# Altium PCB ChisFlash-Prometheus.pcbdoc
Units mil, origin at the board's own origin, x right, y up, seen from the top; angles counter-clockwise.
Board outline 4825.59 x 2046 mil, 2 copper layers (Top Layer, Bottom Layer); 14 components, 55 nets, 238 pads, 204 vias.
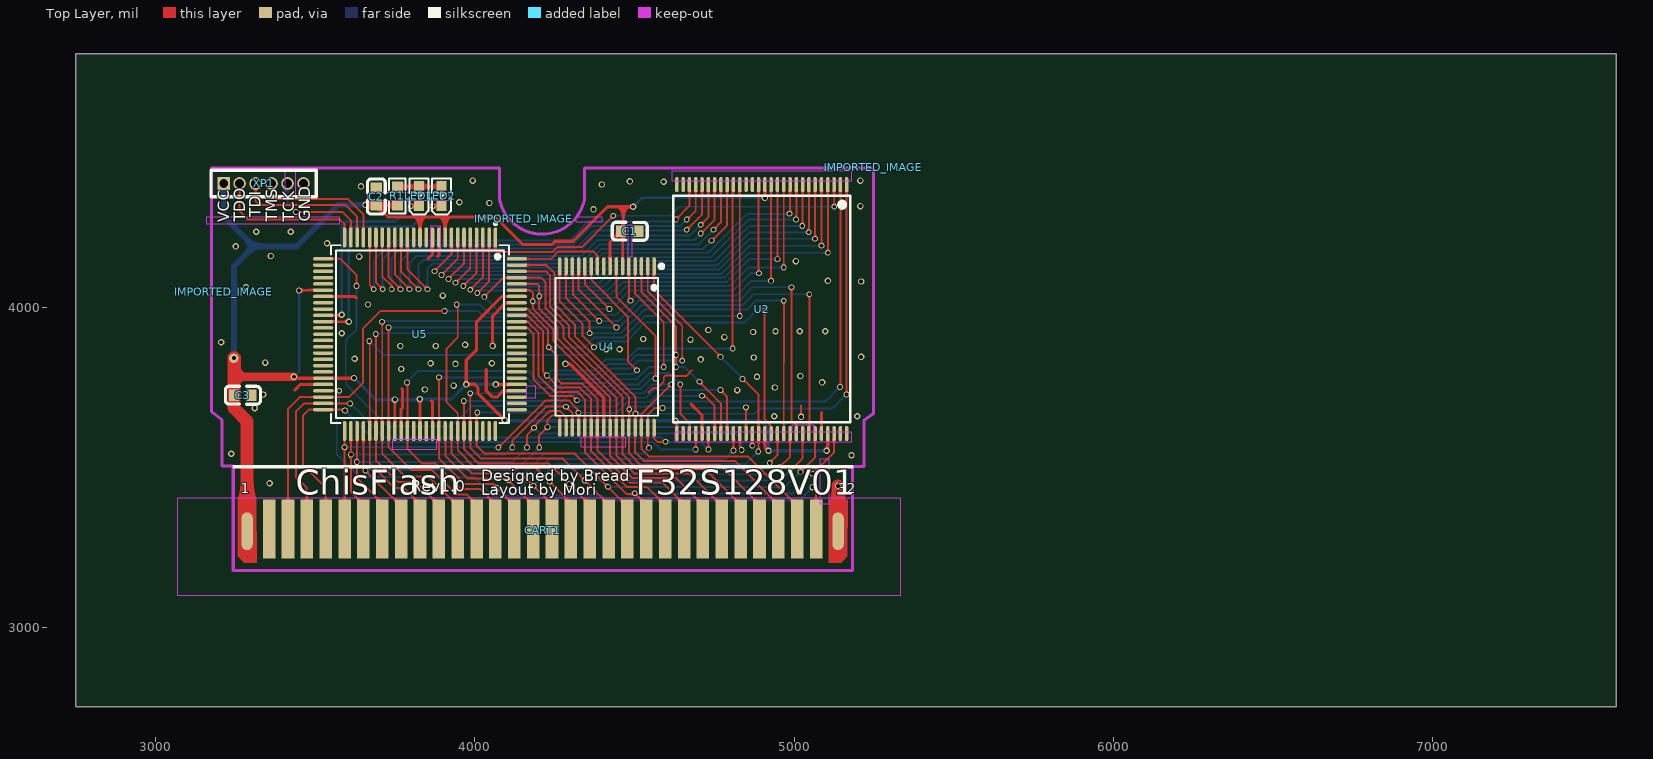
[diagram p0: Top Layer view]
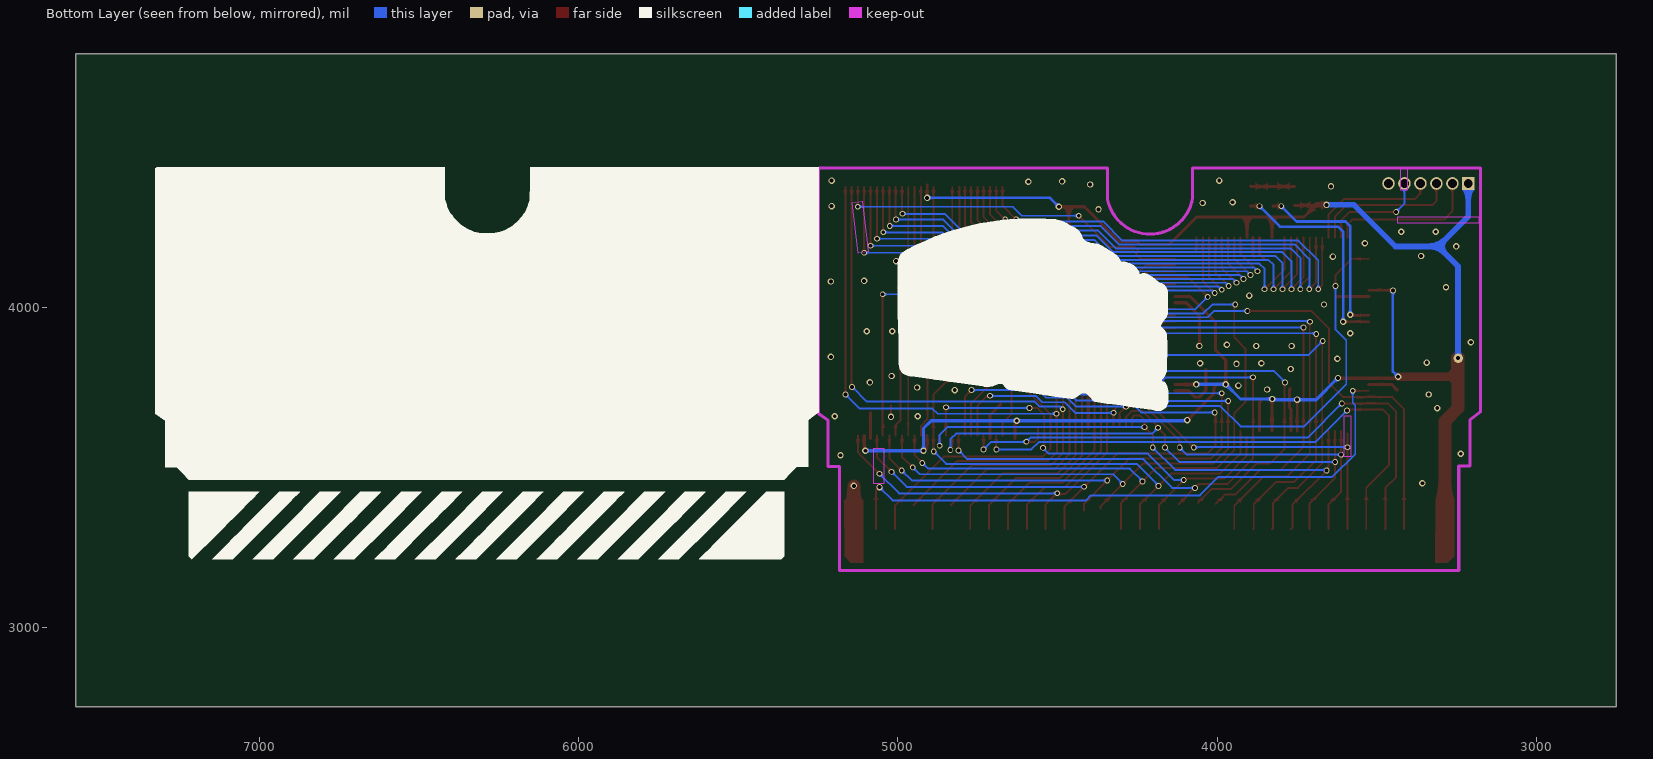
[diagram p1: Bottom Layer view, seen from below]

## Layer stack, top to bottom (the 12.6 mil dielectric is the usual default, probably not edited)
Top Layer: signal copper (thickness not stored)
Dielectric: dielectric 12.6, FR-4, Dk 4.8
Bottom Layer: signal copper (thickness not stored)

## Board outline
7575.59,2750 2750,2750 2750,4796 7575.59,4796

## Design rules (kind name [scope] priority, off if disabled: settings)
Clearance copperThickness1oz [All] p1: gap=7 ignorepadtopadclearanceinfootprint=FALSE except(6: Track-Track Track-SMDPad SMDPad-SMDPad Track-THPad SMDPad-THPad THPad-THPad Track-Via SMDPad-Via THPad-Via Via-Via Track-Fill SMDPad-Fill THPad-Fill Via-Fill Fill-Fill Track-Region SMDPad-Region THPad-Region Via-Region Fill-Region Region-Region Track-Poly SMDPad-Poly THPad-Poly Via-Poly Fill-Poly Region-Poly Poly-Poly SMDPad-Text THPad-Text Via-Text Fill-Text Region-Text Poly-Text Text-Text Track-Sheet SMDPad-Sheet THPad-Sheet Via-Sheet Fill-Sheet Region-Sheet Poly-Sheet Track-Hole SMDPad-Hole THPad-Hole Via-Hole Fill-Hole Region-Hole Poly-Hole Text-Hole Sheet-Hole; 11.8: Track-Text Text-Sheet)
Clearance copperThickness2oz [All] p1: gap=7 ignorepadtopadclearanceinfootprint=FALSE except(6: Track-Track Track-SMDPad SMDPad-SMDPad Track-THPad SMDPad-THPad THPad-THPad Track-Via SMDPad-Via THPad-Via Via-Via Track-Fill SMDPad-Fill THPad-Fill Via-Fill Fill-Fill Track-Region SMDPad-Region THPad-Region Via-Region Fill-Region Region-Region Track-Poly SMDPad-Poly THPad-Poly Via-Poly Fill-Poly Region-Poly Poly-Poly SMDPad-Text THPad-Text Via-Text Fill-Text Region-Text Poly-Text Text-Text Track-Sheet SMDPad-Sheet THPad-Sheet Via-Sheet Fill-Sheet Region-Sheet Poly-Sheet Track-Hole SMDPad-Hole THPad-Hole Via-Hole Fill-Hole Region-Hole Poly-Hole Text-Hole Sheet-Hole; 11.8: Track-Text Text-Sheet)
DiffPairsRouting differentialPair [All] p1: maxuncoupledlength=10 maxlimit=6 mostfreqgap=6 toplayer_minwidth=6 toplayer_prefwidth=10 toplayer_maxwidth=100 bottomlayer_minwidth=6 bottomlayer_prefwidth=10 bottomlayer_maxwidth=100
PasteMaskExpansion pasteMaskExpansion [All] p1:
PlaneConnect innerPlane [All] p1: planeconnectstyle=Relief reliefexpansion=20 reliefentries=4 reliefconductorwidth=10 reliefairgap=10
PolygonConnect copperRegion [All] p1: connectstyle=Direct reliefentries=4 reliefconductorwidth=10 polygonreliefangle="90 Angle" airgapwidth=10
RoutingVias viaSize [All] p1: viastyle="Through Hole" holewidth=12 minholewidth=12 maxholewidth=248 width=20 minwidth=16 maxwidth=393.7
SolderMaskExpansion solderMaskExpansion [All] p1: useseparateexpansions=TRUE expansion=2 expansionbottom=2
Width copperThickness1oz [All] p1: maxlimit=100 minlimit=6 preferedwidth=8
Width copperThickness2oz [All] p1: maxlimit=100 minlimit=6 preferedwidth=10

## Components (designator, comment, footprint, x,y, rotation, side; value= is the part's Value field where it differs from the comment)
C1 "CAP_0603" C0603 4485.31,4239.47 r180 top
C2 "CAP_0603" C0603 3692,4348 r270 top
C3 "CL10A106MA8NRNC" C0603 3274,3726 r180 top
CART1 "GBACartridge" GBACartridge 4211.7,3889.15 r0 top
IMPORTED_IMAGE "IMPORTED_IMAGE" IMPORTED_IMAGE 4154.24,4279.04 r0 top
IMPORTED_IMAGE "IMPORTED_IMAGE" IMPORTED_IMAGE 3214,4050 r0 top
IMPORTED_IMAGE "IMPORTED_IMAGE" IMPORTED_IMAGE 5248.42,4440.47 r0 top
LED1 "NCD0603B1" LED0603-RD 3826,4350 r90 top
LED2 "NCD0603G1" LED0603-RD 3896,4350 r90 top
R1 "0603WAF1001T5E" R0603 3758,4350 r270 top
U2 "S29GL256S10TFI010" TSOP-56_L18.4-W14.0-P0.50-LS20.0-TL 4899,3995.75 r270 top
U4 "={Manufacturer Part}" STSOP-32_L8.0-W11.8-P0.50-LS13.4-TL 4414,3877 r270 top
U5 "EPM240T100C5N" TQFP-100_L14.0-W14.0-P0.50-LS16.0-BL 3828.79,3917 r180 top
XP1 "jtag" HDR-TH_6P-P1.27-V-M-1 3339,4389 r0 top

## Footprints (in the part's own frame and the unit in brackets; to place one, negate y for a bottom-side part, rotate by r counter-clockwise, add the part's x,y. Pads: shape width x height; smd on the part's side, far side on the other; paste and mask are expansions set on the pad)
C0603 [mm]
  rect 0.8x0.9 smd: 1(-0.7,0) 2(0.7,0)
  silkscreen extent -1.41,-0.71 1.39,0.72
GBACartridge [mm]
  oval 0.905x2.997 smd: 1(-23.479,-14.958)
  rect 1x4.691 smd: 2(-21.724,-14.805) 3(-20.224,-14.805) 4(-18.724,-14.805) 5(-17.224,-14.805) 6(-15.724,-14.805) 7(-14.224,-14.805) 8(-12.724,-14.805) 9(-11.224,-14.805) 10(-9.724,-14.805) 11(-8.224,-14.805) 12(-6.724,-14.805) 13(-5.224,-14.805) 14(-3.724,-14.805) 15(-2.224,-14.805) 16(-0.724,-14.805) 17(0.776,-14.805) 18(2.276,-14.805) 19(3.776,-14.805) 20(5.276,-14.805) 21(6.776,-14.805) 22(8.276,-14.805) 23(9.776,-14.805) 24(11.276,-14.805) 25(12.776,-14.805) 26(14.276,-14.805) 27(15.776,-14.805) 28(17.276,-14.805) 29(18.776,-14.805) 30(20.276,-14.805) 31(21.776,-14.805)
  oval 0.904x3.008 smd: 32(23.529,-14.966)
  Top Layer region: 22.775,-17.473 22.782,-12.46 24.282,-12.46 24.275,-16.973 23.775,-17.473
  Top Layer region: -22.733,-12.46 -22.725,-17.456 -23.725,-17.456 -24.224,-16.956 -24.233,-12.46
HDR-TH_6P-P1.27-V-M-1 [mm]
  rect 1x1 hole 0.7: 1(-3.175,0)
  round 1 hole 0.7: 2(-1.905,0) 3(-0.635,0) 4(0.635,0) 5(1.905,0) 6(3.175,0)
  silkscreen extent -4.18,-1.05 4.19,1.05
IMPORTED_IMAGE [mil]
LED0603-RD [mm]
  rect 0.8x0.8 smd: 1(-0.799,0) 2(0.799,0)
  silkscreen extent -1.49,-0.75 1.39,0.76
R0603 [mil]
  rect 31.75x34.02 smd: 1(-29.66,0) 2(29.66,0)
  silkscreen extent -55,-26 55,26
STSOP-32_L8.0-W11.8-P0.50-LS13.4-TL [mm]
  oval 1.44x0.28 smd: 1(-6.42,3.75) 2(-6.42,3.25) 3(-6.42,2.75) 4(-6.42,2.25) 5(-6.42,1.75) 6(-6.42,1.25) 7(-6.42,0.75) 8(-6.42,0.25) 9(-6.42,-0.25) 10(-6.42,-0.75) 11(-6.42,-1.25) 12(-6.42,-1.75) 13(-6.42,-2.25) 14(-6.42,-2.75) 15(-6.42,-3.25) 16(-6.42,-3.75) 17(6.42,-3.75) 18(6.42,-3.25) 19(6.42,-2.75) 20(6.42,-2.25) 21(6.42,-1.75) 22(6.42,-1.25) 23(6.42,-0.75) 24(6.42,-0.25) 25(6.42,0.25) 26(6.42,0.75) 27(6.42,1.25) 28(6.42,1.75) 29(6.42,2.25) 30(6.42,2.75) 31(6.42,3.25) 32(6.42,3.75)
  silkscreen extent -6.57,-4.08 5.47,4.49
TQFP-100_L14.0-W14.0-P0.50-LS16.0-BL [mm]
  oval 0.28x1.6 smd: 1(-6,-7.7) 2(-5.5,-7.7) 3(-5,-7.7) 4(-4.5,-7.7) 5(-4,-7.7) 6(-3.5,-7.7) 7(-3,-7.7) 8(-2.5,-7.7) 9(-2,-7.7) 10(-1.5,-7.7) 11(-1,-7.7) 12(-0.5,-7.7) 13(0,-7.7) 14(0.5,-7.7) 15(1,-7.7) 16(1.5,-7.7) 17(2,-7.7) 18(2.5,-7.7) 19(3,-7.7) 20(3.5,-7.7) 21(4,-7.7) 22(4.5,-7.7) 23(5,-7.7) 24(5.5,-7.7) 25(6,-7.7) 51(6,7.7) 52(5.5,7.7) 53(5,7.7) 54(4.5,7.7) 55(4,7.7) 56(3.5,7.7) 57(3,7.7) 58(2.5,7.7) 59(2,7.7) 60(1.5,7.7) 61(1,7.7) 62(0.5,7.7) 63(0,7.7) 64(-0.5,7.7) 65(-1,7.7) 66(-1.5,7.7) 67(-2,7.7) 68(-2.5,7.7) 69(-3,7.7) 70(-3.5,7.7) 71(-4,7.7) 72(-4.5,7.7) 73(-5,7.7) 74(-5.5,7.7) 75(-6,7.7)
  oval 1.6x0.28 smd: 26(7.7,-6) 27(7.7,-5.5) 28(7.7,-5) 29(7.7,-4.5) 30(7.7,-4) 31(7.7,-3.5) 32(7.7,-3) 33(7.7,-2.5) 34(7.7,-2) 35(7.7,-1.5) 36(7.7,-1) 37(7.7,-0.5) 38(7.7,0) 39(7.7,0.5) 40(7.7,1) 41(7.7,1.5) 42(7.7,2) 43(7.7,2.5) 44(7.7,3) 45(7.7,3.5) 46(7.7,4) 47(7.7,4.5) 48(7.7,5) 49(7.7,5.5) 50(7.7,6) 76(-7.7,6) 77(-7.7,5.5) 78(-7.7,5) 79(-7.7,4.5) 80(-7.7,4) 81(-7.7,3.5) 82(-7.7,3) 83(-7.7,2.5) 84(-7.7,2) 85(-7.7,1.5) 86(-7.7,1) 87(-7.7,0.5) 88(-7.7,0) 89(-7.7,-0.5) 90(-7.7,-1) 91(-7.7,-1.5) 92(-7.7,-2) 93(-7.7,-2.5) 94(-7.7,-3) 95(-7.7,-3.5) 96(-7.7,-4) 97(-7.7,-4.5) 98(-7.7,-5) 99(-7.7,-5.5) 100(-7.7,-6)
  silkscreen extent -7.08,-8.9 7.08,7.08
TSOP-56_L18.4-W14.0-P0.50-LS20.0-TL [mil]
  oval 47.2x11 smd: 1(-389.8,265.8) 2(-389.8,246.1) 3(-389.8,226.4) 4(-389.8,206.7) 5(-389.8,187) 6(-389.8,167.3) 7(-389.8,147.6) 8(-389.8,128) 9(-389.8,108.3) 10(-389.8,88.6) 11(-389.8,68.9) 12(-389.8,49.2) 13(-389.8,29.5) 14(-389.8,9.8) 15(-389.8,-9.8) 16(-389.8,-29.5) 17(-389.8,-49.2) 18(-389.8,-68.9) 19(-389.8,-88.6) 20(-389.8,-108.3) 21(-389.8,-127.9) 22(-389.8,-147.6) 23(-389.8,-167.3) 24(-389.8,-187) 25(-389.8,-206.7) 26(-389.8,-226.4) 27(-389.8,-246.1) 28(-389.8,-265.7) 29(389.8,-265.7) 30(389.8,-246.1) 31(389.8,-226.4) 32(389.8,-206.7) 33(389.8,-187) 34(389.8,-167.3) 35(389.8,-147.6) 36(389.8,-127.9) 37(389.8,-108.3) 38(389.8,-88.6) 39(389.8,-68.9) 40(389.8,-49.2) 41(389.8,-29.5) 42(389.8,-9.8) 43(389.8,9.8) 44(389.8,29.5) 45(389.8,49.2) 46(389.8,68.9) 47(389.8,88.6) 48(389.8,108.3) 49(389.8,128) 50(389.8,147.6) 51(389.8,167.3) 52(389.8,187) 53(389.8,206.7) 54(389.8,226.4) 55(389.8,246.1) 56(389.8,265.8)
  silkscreen extent -354,-278 354,278

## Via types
v1: diameter 18, hole 12, Top Layer to Bottom Layer, 122 vias
v2: diameter 20, hole 12, Top Layer to Bottom Layer, 81 vias
v3: diameter 30, hole 12, Top Layer to Bottom Layer, 1 vias

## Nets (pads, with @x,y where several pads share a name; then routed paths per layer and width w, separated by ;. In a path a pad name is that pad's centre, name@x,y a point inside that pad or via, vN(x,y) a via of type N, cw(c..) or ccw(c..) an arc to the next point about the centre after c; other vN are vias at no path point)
$1N77583: LED1.2 LED2.2 R1.1 | length 138.8
  Top Layer w10: R1.1 3894.18,4379.66 LED2.2
A16: CART1.22 U2.54 U4.21 U5.90 | length 1628.9
  Top Layer w6: U5.90 4165.63,3956.37 4200,3922 4200,3786 4250,3736 4322.37,3736 4345.1,3713.27 U4.21 4345.1,3546.9 4476,3416 4498.56,3416 v1(4501.3,3418.74) 4502.63,3418.74 4537.51,3383.86 CART1.22 ; v1(5058,3480) 5125.4,3547.4 U2.54@5125.4,3599.2
  Bottom Layer w6: v1(4501.3,3418.74) 4996.74,3418.74 v1(5058,3480)
A17: CART1.23 U2.19 U4.22 U5.91 | length 2080.5
  Top Layer w6: U5.91 4163.94,3976.06 4214,3926 4214,3800 v1(4226,3788) 4264,3750 4329.24,3750 4364.79,3714.44 U4.22 4364.79,3551.21 4477.66,3438.34 4540.39,3438.34 4596.56,3382.17 CART1.23 ; v1(4808,3872) 4808,4376.4 U2.19@4810.4,4378.8
  Bottom Layer w6: v1(4226,3788) 4241.53,3803.53 4375.53,3803.53 4410,3838 4476,3838 4510,3872 v1(4808,3872)
A18: CART1.24 U2.18 U4.23 U5.92 | length 2067
  Top Layer w6: U5.92 4132.2,3996 4164,3996 4229.06,3930.94 4229.06,3878.94 v1(4232,3876) 4258,3850 4258,3776 4272,3762 4337.41,3762 4384.47,3714.94 U4.23 4384.47,3553.53 4486.24,3451.76 4588.24,3451.76 4655.62,3384.38 CART1.24 ; v1(4830,3974) 4830.1,3974.1 U2.18@4830.1,4378.8
  Bottom Layer w6: v1(4232,3876) 4344,3876 4375,3907 4467,3907 4534,3974 v1(4830,3974)
A19: CART1.25 U2.11 U4.25 U5.95 | length 2182.6
  Top Layer w6: U5.95 4173.32,4054.8 4182,4046.12 v1(4182,4020) 4182,3997.28 4246,3933.28 4246,3896 4423.84,3718.16 U4.25 4423.84,3536.16 4493.87,3466.13 4631.87,3466.13 4714.67,3383.33 CART1.25 ; v1(4967.9,4126) U2.11@4967.9,4378.8
  Bottom Layer w6: v1(4182,4020) 4188,4014 4228,4014 4244,4030 4438,4030 4476,4068 4800,4068 4858,4126 v1(4967.9,4126)
A20: CART1.26 U2.12 U4.26 U5.96 | length 2193.1
  Top Layer w6: U5.96 4195.52,4074.48 4202,4068 v1(4202,4036) 4202,3997.17 4260,3939.17 4260,3902 4443.53,3718.47 U4.26 4443.53,3538.47 4501.51,3480.49 4673.51,3480.49 4773.73,3380.27 CART1.26 ; v1(4948.2,4152) U2.12@4948.2,4378.8
  Bottom Layer w6: v1(4202,4036) 4208,4042 4426,4042 4464,4080 4788,4080 4860,4152 v1(4948.2,4152)
A21: CART1.27 U2.15 U4.27 U5.97 | length 2493.9
  Top Layer w6: v1(4030,4034) 4090.17,4094.17 U5.97 4207.83,4094.17 4222,4080 4222,3998 4278,3942 4278,3906 4463.21,3720.79 U4.27 4463.21,3540.79 4509.75,3494.25 4722.41,3494.25 CART1.27@4835.16,3381.49 ; U2.15@4889.2,4378.8 4889.2,4108.8 v1(4890,4108)
  Bottom Layer w6: v1(4030,4034) 4069,3995 4231,3995 4250,4014 4446,4014 4486,4054 4810,4054 4864,4108 v1(4890,4108)
A22: CART1.28 U2.2 U4.28 U5.98 | length 2637.6
  Top Layer w6: U5.98 4222.15,4113.85 4236,4100 4236,4003.32 4296,3943.32 4296,3908 4483.91,3720.09 4483.91,3682 4483.91,3625.25 U4.28 4482.9,3545.1 4520.72,3507.28 4768.72,3507.28 4891.84,3384.16 CART1.28 ; v1(5144,3752) 5145.1,3753.1 U2.2@5145.1,4378.8
  Bottom Layer w6: v1(4484,3682) 4492,3690 4556,3690 4572,3706 5098,3706 v1(5144,3752)
A23: CART1.29 U2.1 U4.29 U5.99 | length 2647.9
  Top Layer w6: U5.99 4224.46,4133.54 4250,4108 4250,4010.9 4314,3946.9 4314,3910 4504,3720 v1(4504,3668) 4504,3625.65 U4.29 4502.58,3547.42 4529.81,3520.19 4813.81,3520.19 CART1.29@4951.25,3382.74 ; v1(5164,3728) 5164.8,3728.8 U2.1@5164.8,4378.8
  Bottom Layer w6: v1(4504,3668) 4876,3668 4892,3684 5120,3684 v1(5164,3728)
AD0: CART1.6 U2.35 U4.20 U5.51 | length 1714.6
  Top Layer w6: CART1.6 U5.51@3592.63,3605.85 ; v1(4074,3562) 4222,3710 4294.06,3710 4324.69,3679.36 v1(4324.69,3670.88) 4325.42,3670.15 U4.20@4325.42,3626.24 ; v1(4712,3724) 4720,3724 4751.4,3692.6 U2.35@4751.4,3599.2
  Bottom Layer w6: v1(3592.73,3563.15) 4072.85,3563.15 v1(4074,3562) ; v1(4324.69,3670.88) 4444.88,3670.88 4478,3704 4548,3704 4568,3724 v1(4712,3724)
AD1: CART1.7 U2.37 U4.19 U5.52 | length 1801.6
  Top Layer w6: U5.52@3612.27,3613.82 v1(3612.27,3539.78) 3612.27,3423.73 3651.68,3384.32 CART1.7 ; v1(4118,3562) 4118,3584 4224,3690 v1(4286,3690) 4305.73,3670.27 U4.19@4305.73,3626.24 ; v1(4770,3742) 4790.7,3721.3 U2.37@4790.7,3599.2
  Bottom Layer w6: v1(3612.27,3539.78) 4095.78,3539.78 v1(4118,3562) ; v1(4286,3690) 4442,3690 4470,3718 4536,3718 4560,3742 v1(4770,3742)
AD2: CART1.8 U2.39 U4.18 U5.53 | length 1872.4
  Top Layer w6: U5.53 3631.94,3466.06 3710.74,3387.26 CART1.8 ; v1(4164,3562) 4164,3602 v1(4186,3624) 4186,3628 4234,3676 4267.49,3676 4286.05,3657.44 U4.18@4286.05,3626.24 ; U2.39@4830.1,3599.2 4830.1,3559.9 v1(4836,3554)
  Bottom Layer w6: v1(3631.04,3516.86) 4118.86,3516.86 v1(4164,3562) ; v1(4186,3624) 4204,3606 4818,3606 4836,3588 v1(4836,3554)
AD3: CART1.9 U2.41 U4.17 U5.54 | length 1823.8
  Top Layer w6: U5.54 3651.62,3496.2 v1(3657.67,3490.15) 3764,3383.81 3764,3312.05 CART1.9 ; v1(4202,3562) 4202,3600 v1(4228,3626) 4228,3648 4242,3662 4262,3662 4266.36,3657.64 U4.17 ; v1(4869.55,3567.83) U2.41@4869.55,3599.15
  Bottom Layer w6: v1(3657.67,3490.15) 3659.55,3492.03 4132.03,3492.03 v1(4202,3562) ; v1(4228,3626) 4845.62,3626 4869.55,3602.07 v1(4869.55,3567.83)
AD4: CART1.10 U2.44 U4.16 U5.55 | length 2689.5
  Top Layer w6: v1(3670,3896) 3671.31,3894.69 U5.55 3671.31,3512.69 3748,3436 3778,3436 3826,3388 3826,3309.11 CART1.10 ; U4.16@4266,4132.12 4266,4020 4338,3948 4338,3912 v1(4374,3876) ; v1(4908,3992) 4908,3650 4928.5,3629.5 U2.44@4928.5,3599.2
  Bottom Layer w6: v1(3670,3896) 3714,3852 4350,3852 v1(4374,3876) 4392,3894 4474,3894 4534,3954 4846,3954 4884,3992 v1(4908,3992)
AD5: CART1.11 U2.46 U4.15 U5.56 | length 2713.3
  Top Layer w6: v1(3690,3918) 3690.99,3917.01 U5.56 3690.99,3523.01 3760.13,3453.87 3817.01,3453.87 3886,3384.88 3886,3308.16 CART1.11 ; U4.15@4285.99,4131.71 4285.99,4030.01 4359.99,3956.01 v1(4360,3920) ; U2.46@4967.9,3599.2 4967.9,3828.39 4968,3828.49 v1(4968,4022)
  Bottom Layer w6: v1(3690,3918) 3692,3920 v1(4360,3920) 4458,3920 4532,3994 4852,3994 4880,4022 v1(4968,4022)
AD6: CART1.12 U2.48 U4.14 U5.57 | length 2800.2
  Top Layer w6: v1(3710,3956) 3710.68,3955.32 U5.57 3710.68,3542.54 3781.35,3471.87 3855.25,3471.87 3946.96,3380.17 CART1.12 ; U4.14@4304,4133.49 4308,4129.49 4308,4040 v1(4390,3958) ; v1(4992,4064) 4992,3648 5007.3,3632.7 U2.48@5007.3,3599.2
  Bottom Layer w6: v1(3710,3956) 3712,3958 v1(4390,3958) 4449.46,3958 4513.46,4022 4827.82,4022 4869.82,4064 v1(4992,4064)
AD7: CART1.13 U2.50 U4.13 U5.58 | length 2770.4
  Top Layer w6: v1(3730,3938) 3730.36,3937.64 U5.58 3730.36,3563.64 3802,3492 3866,3492 3942.75,3415.25 3975.1,3415.25 CART1.13@4005.02,3385.32 ; U4.13@4325.42,4131.76 4325.42,4056.58 v1(4444,3938) ; U2.50@5046.6,3599.2 5048,3600.6 v1(5048,4042)
  Bottom Layer w6: v1(3730,3938) v1(4444,3938) 4452.49,3938 4522.49,4008 4838,4008 4872,4042 v1(5048,4042)
AD8: CART1.14 U2.36 U4.3 U5.61 | length 2110.1
  Top Layer w6: v1(3788,3766) 3789.42,3764.58 U5.61 3789.42,3558.58 3836,3512 3878,3512 3958.05,3431.95 4018.35,3431.95 4059.69,3390.61 CART1.14@4059.69,3387.88 ; U4.3@4522.27,4131.76 4522.27,4049.73 4630,3942 v1(4630,3852) v1(4630,3814) ; v1(4704,3768) 4771.1,3700.9 U2.36@4771.1,3599.2
  Bottom Layer w6: v1(3788,3766) 3824,3802 4168,3802 4204,3766 4234,3766 4258.77,3790.77 4382.77,3790.77 4416,3824 4480,3824 4508,3852 v1(4630,3852) ; v1(4630,3814) 4658,3814 v1(4704,3768)
AD9: CART1.15 U2.38 U4.2 U5.66 | length 2536.2
  Top Layer w6: v1(3888,3782) 3887.84,3781.84 U5.66 3887.84,3528.16 3968.04,3447.96 4057.85,3447.96 v1(4070.15,3435.67) 4120.91,3384.91 CART1.15@4120.91,3383.98 ; U4.2@4542,4131.71 4542,4052 4650,3944 v1(4650,3834) ; v1(4810.12,3553.09) 4810.4,3553.37 U2.38@4810.4,3599.2
  Bottom Layer w6: v1(3888,3782) 4162,3782 4196,3748 4238,3748 4266.66,3776.66 4390.66,3776.66 4424,3810 4486,3810 4510,3834 v1(4650,3834) ; v1(4070.15,3435.67) 4141.67,3435.67 4231.64,3525.64 4782.67,3525.64 v1(4810.12,3553.09)
AD10: 
AD11: CART1.17 U2.42 U4.1 U5.68 | length 1993
  Top Layer w6: U5.68 3927.21,3544.79 3990.64,3481.36 4144.64,3481.36 v1(4184,3442) 4242.23,3383.77 CART1.17 ; U4.1 4561.64,4054.36 v1(4770,3846) ; v1(4839.07,3776.93) 4889.2,3726.8 4889.2,3615.2 4889.2,3551.2 v1(4888,3550)
  Bottom Layer w6: v1(4184,3442) 4253.1,3511.1 4849.1,3511.1 v1(4888,3550) ; v1(4770,3846) v1(4839.07,3776.93)
AD12: CART1.18 U2.45 U4.12 U5.69 | length 2462.2
  Top Layer w6: v1(3944,4010) 3946.9,4007.1 3946.9,3906.9 3912,3872 3912,3704 3946.9,3669.1 U5.69 3946.9,3553.1 4002.54,3497.46 4192.54,3497.46 v1(4234,3456) 4301.29,3388.71 CART1.18 ; U4.12 4345.1,4072.9 v1(4422,3996) ; v1(4924,3514) 4948.2,3538.2 U2.45@4948.2,3599.2
  Bottom Layer w6: v1(3944,4010) 4015.53,4010 4043.53,3982 4238,3982 4252,3996 v1(4422,3996) ; v1(4234,3456) 4273.95,3495.95 4905.95,3495.95 v1(4924,3514)
AD13: CART1.19 U2.47 U4.4 U5.70 | length 2447.6
  Top Layer w6: v1(3966,3708) 3966.58,3707.42 U5.70 3966.58,3557.42 4011.68,3512.32 4231.68,3512.32 v1(4296,3448) 4365.83,3378.17 CART1.19@4365.83,3370.27 ; U4.4 4502.58,4043.42 4592,3954 v1(4592,3814) ; v1(4954,3500) 4987.6,3533.6 U2.47@4987.6,3599.2
  Bottom Layer w6: v1(3966,3708) 4236,3708 4280,3752 4420,3752 4444,3776 4506,3776 4544,3814 v1(4592,3814) ; v1(4296,3448) 4326.34,3478.34 4932.34,3478.34 v1(4954,3500)
AD14: CART1.20 U2.49 U4.11 U5.71 | length 2399.1
  Top Layer w6: v1(3986,3732) 3986.27,3731.73 U5.71 ; U5.71@3986.74,3598.42 3986.74,3561.26 4020.34,3527.66 4275.97,3527.66 v1(4344.66,3458.97) 4417.24,3386.39 CART1.20@4417.24,3364.13 ; U4.11 4366,4128.55 4366,4086 4480,3972 4480,3832 v1(4508,3804) ; v1(4988,3490) 5027,3529 U2.49@5027,3599.2
  Bottom Layer w6: v1(3986,3732) 4242,3732 4274,3764 4412,3764 4440,3792 4496,3792 v1(4508,3804) ; v1(4344.66,3458.97) 4956.97,3458.97 v1(4988,3490)
AD15: CART1.21 U2.51 U4.7 U5.72 | length 2486.7
  Top Layer w6: v1(4008,3672) 4005.95,3669.95 U5.72 4005.95,3568.05 4030.96,3543.04 4313.08,3543.04 v1(4417.09,3439.04) 4478.45,3377.67 CART1.21 ; U4.7 4443.53,4034.47 4566,3912 v1(4566,3778) ; v1(5020,3486) 5066.3,3532.3 U2.51@5066.3,3599.2
  Bottom Layer w6: v1(4008,3672) 4238.54,3672 4294.54,3728 4438,3728 4456,3746 4520,3746 4552,3778 v1(4566,3778) ; v1(4417.09,3439.04) 4973.04,3439.04 v1(5020,3486)
BK: U4.10 U5.100 | length 300.9
  Top Layer w6: U5.100 4239.22,4153.22 4262,4176 4372,4176 4384,4164 4384,4130.23 U4.10
FA0: U2.31 U5.26 | length 1841.2
  Top Layer w6: U5.26 3578.78,4153.22 3630,4102 v1(3630,4068) ; v1(4644,3760) 4644,3668 4672.6,3639.4 U2.31@4672.6,3599.2
  Bottom Layer w6: v1(3630,4068) 3630,3932 3596.31,3898.31 3596.31,3759.69 3728,3628 3927.16,3628 3991.16,3692 4238,3692 4286,3740 4428,3740 4448,3760 4514,3760 4550,3796 4608,3796 v1(4644,3760)
FA1: U2.26 U5.21 | length 1376.9
  Top Layer w6: U5.21 3671.31,4070.69 v1(3684,4058) ; v1(4630,4276) 4672.6,4318.6 U2.26@4672.6,4378.8
  Bottom Layer w6: v1(3684,4058) 3684,4148 3746,4210 4298,4210 4358,4270 4624,4270 v1(4630,4276)
FA2: U2.25 U5.20 | length 1382.7
  Top Layer w6: U5.20 3690.99,4079.01 v1(3712,4058) ; v1(4664,4276) 4692.3,4304.3 U2.25@4692.3,4378.8
  Bottom Layer w6: v1(3712,4058) 3712,4152 3758,4198 4308,4198 4366,4256 4644,4256 v1(4664,4276)
FA3: U2.24 U5.19 | length 1387.4
  Top Layer w6: U5.19 3710.68,4097.32 3740,4068 v1(3740,4058) ; v1(4664,4244) 4712,4292 U2.24@4712,4378.8
  Bottom Layer w6: v1(3740,4058) 3740,4156 3770,4186 4318,4186 4374,4242 4662,4242 v1(4664,4244)
FA4: U2.23 U5.18 | length 1381.6
  Top Layer w6: U5.18 3730.36,4095.64 v1(3768,4058) ; v1(4708,4260) 4731.7,4283.7 U2.23@4731.7,4378.8
  Bottom Layer w6: v1(3768,4058) 3768,4146 3796,4174 4326,4174 4378,4226 4674,4226 v1(4708,4260)
FA5: U2.22 U5.17 | length 1378.1
  Top Layer w6: U5.17 3750.05,4103.95 v1(3796,4058) ; v1(4708,4232) 4751.4,4275.4 U2.22@4751.4,4378.8
  Bottom Layer w6: v1(3796,4058) 3796,4140 3818,4162 4336,4162 4386,4212 4688,4212 v1(4708,4232)
FA6: U2.21 U5.16 | length 1374.6
  Top Layer w6: U5.16 3769.73,4112.27 v1(3824,4058) ; v1(4748,4244) 4771.1,4267.1 U2.21@4771.1,4378.8
  Bottom Layer w6: v1(3824,4058) 3824,4134 3840,4150 4344,4150 4392,4198 4702,4198 v1(4748,4244)
FA7: U2.20 U5.15 | length 1367.5
  Top Layer w6: U5.15 3789.42,4120.58 v1(3852,4058) ; v1(4742,4210) 4790.7,4258.7 U2.20@4790.7,4378.8
  Bottom Layer w6: v1(3852,4058) 3852,4122 3868,4138 4350,4138 4396,4184 4716,4184 v1(4742,4210)
FA8: U2.10 U5.8 | length 1400.2
  Top Layer w6: v1(3874,4114) 3927.21,4167.21 U5.8 ; v1(4986,4294) 4987.6,4295.6 U2.10@4987.6,4378.8
  Bottom Layer w6: v1(3874,4114) 3886,4126 4358,4126 4404,4172 4732,4172 4854,4294 v1(4986,4294)
FA9: U2.9 U5.7 | length 1424.6
  Top Layer w6: v1(3896,4102) 3946.9,4152.9 U5.7 ; v1(5006,4276) 5007.3,4277.3 U2.9@5007.3,4378.8
  Bottom Layer w6: v1(3896,4102) 3908,4114 4366,4114 4410,4158 4740,4158 4858,4276 v1(5006,4276)
FA10: U2.8 U5.6 | length 1450.2
  Top Layer w6: v1(3918,4090) 3966.58,4138.58 U5.6 ; v1(5026,4256) 5027,4257 U2.8@5027,4378.8
  Bottom Layer w6: v1(3918,4090) 3930,4102 4374,4102 4418,4146 4750,4146 4860,4256 v1(5026,4256)
FA11: U2.7 U5.5 | length 1475.8
  Top Layer w6: v1(3940,4078) 3986.27,4124.27 U5.5 ; v1(5046,4236) 5046.6,4236.6 U2.7@5046.6,4378.8
  Bottom Layer w6: v1(3940,4078) 3952,4090 4382,4090 4424,4132 4758,4132 4862,4236 v1(5046,4236)
FA12: U2.6 U5.4 | length 1495.8
  Top Layer w6: v1(3964,4068) 4005.95,4109.95 U5.4 ; v1(5066,4216) 5066.3,4216.3 U2.6@5066.3,4378.8
  Bottom Layer w6: v1(3964,4068) 3974,4078 4392,4078 4434,4120 4766,4120 4862,4216 v1(5066,4216)
FA13: U2.5 U5.3 | length 1522.5
  Top Layer w6: v1(3986,4056) 4025.64,4095.64 U5.3 ; v1(5086,4194) U2.5@5086,4378.8
  Bottom Layer w6: v1(3986,4056) 3996,4066 4404,4066 4444,4106 4774,4106 4862,4194 v1(5086,4194)
FA14: U2.4 U5.2 | length 1546.7
  Top Layer w6: v1(4008,4046) 4045.32,4083.32 U5.2 ; U2.4@5105.7,4378.8 5106,4378.5 v1(5106,4172)
  Bottom Layer w6: v1(4008,4046) 4016,4054 4416,4054 4456,4094 4782,4094 4860,4172 v1(5106,4172)
FA15: U2.3 U5.1 | length 1224.9
  Top Layer w6: U5.1 4065.01,4180.99 4072,4174 4243.03,4174 4259.03,4190 4336,4190 v1(4434,4288) ; U2.3@5125.4,4378.8 5126,4378.2 v1(5126,4316)
  Bottom Layer w6: v1(4434,4288) 4612,4288 4640,4316 v1(5126,4316)
GND: C1.1 C2.1 C3.1 CART1.32 U2.33 U2.52 U4.24 U5.10 U5.11 U5.32 U5.46 U5.60 U5.65 U5.79 U5.93 XP1.6 | length 1745.6
  Top Layer w6: 4544,3734 4558,3748 4572,3748 4592,3768 4592,3782 4598,3788 4626,3788 4628,3786 4662,3786 4680,3804 ; v2(5022,3658) 5022,3694
  Top Layer w10: 3436,3742 3453.52,3759.52 U5.46 ; U5.32 3624.89,4035.11 3630,4030 ; U5.60 3769.73,3681.73 3774,3686 3774,3744 3772,3746 ; 3854,4154 3868.16,4168.16 U5.11 ; 3864,3708 3868.16,3703.84 U5.65 ; 3884,4160 3887.84,4163.84 U5.10 ; 4036,3806 4036,3740 4056,3720 4070,3720 4089.84,3739.84 U5.79 ; v2(4056,3880) 4056,3974 4097.43,4015.43 U5.93 ; v2(4284,3824) 4298,3824 4404.16,3717.84 U4.24 ; 4678,3698 4712,3664 4712,3615.2 U2.33@4712,3591.2 ; U2.52@5086,3591.2 5086,3615.2 5086,3672
  Top Layer w40: CART1.32 v2(5138.03,3442)
  other v2: 3358,3450 5180,3538 3237.55,3542.4 4938,3660 5198,3660 3311.3,3685.47 3338.17,3728.27 4822,3742 3844,3744 4940,3750 3934,3756 5088,3766 4884,3784 5020,3786 3770,3808 3940,3824 3862,3826 4054,3826 3344,3828 4708,3838 3624,3840 4874,3844 5210,3846 4412,3870 4454,3870 3767.4,3880 3878,3880 3970,3884 3206,3892 4676,3900 4528,3902 4782,3908 3584,3920 4872,3924 4942,3926 5018,3926 5098,3926 4732,3930 3666,4010 3900,4038 3284,4064 5210,4082 5106,4084 5006,4146 3638,4160 3362,4162 3252,4192 3538,4202 3316,4238 3424,4238 4372,4308 5208,4318 4046,4328 3952,4330 3644,4380 4398.47,4385.88 4591.58,4394.53 4485.89,4395.68 3994,4398 5208,4398
LED1: LED1.1 U5.35 | length 605.1
  Top Layer w8: U5.35 3582.06,3976.06 v2(3584,3978)
  Top Layer w10: v1(3800,4318) 3825.47,4318 LED1.1
  Bottom Layer w8: v2(3584,3978) 3584,4256 3598,4270 3752,4270 v1(3800,4318)
LED2: LED2.1 U5.36 | length 685.9
  Top Layer w8: U5.36 v2@3605.63,3956.37
  Top Layer w10: v2@3605.63,3956.37 v2(3606,3956) ; v1(3868,4318) 3895.47,4318 LED2.1
  Bottom Layer w8: v2(3606,3956) 3606,4238 3622,4254 3804,4254 v1(3868,4318)
REQ: CART1.31 U5.47 | length 1954.8
  Top Layer w6: U5.47 v1(3576,3739.84) ; v2(5058,3438) 5069,3427 CART1.31
  Bottom Layer w6: v1(3576,3739.84) 3576,3701.58 3568.2,3693.77 3568.2,3541.8 3640,3470 3996.87,3470 4054.87,3412 4396,3412 4411.17,3396.83 5016.83,3396.83 v2(5058,3438)
TCK: U5.24 XP1.5 | length 336.5
  Top Layer w6: v1(3440,4300) 3586,4300 3612.25,4273.75 U5.24
  Bottom Layer w6: XP1.5 3414,4326 v1(3440,4300)
TDI: U5.23 XP1.3 | length 457.5
  Top Layer w6: XP1.3 3314,4334 3326,4322 3594,4322 3631.94,4284.06 U5.23
TDO: U5.25 XP1.2 | length 473.7
  Top Layer w6: XP1.2 3264,4302 3290,4276 3578,4276 3592.57,4261.43 U5.25
TMS: U5.22 XP1.4 | length 418
  Top Layer w6: XP1.4 3364,4358 3382,4340 3604,4340 3651.62,4292.38 U5.22
VCC: C1.2 C2.2 C3.2 CART1.1 R1.2 U2.14 U2.29 U2.43 U2.53 U4.6 U4.8 U5.9 U5.13 U5.31 U5.45 U5.59 U5.63 U5.80 U5.94 XP1.1 | length 6578.1
  Top Layer w8: v2(3450,4054) 3450.8,4054.8 U5.31 ; U5.59 v2(3750,3712) ; U4.8 4423.84,4204.57 4457.75,4238.47 C1.2 ; U4.6 4463.21,4234 C1.2 ; 4465.2,4316 4465.2,4246.93 C1.2 ; v2(4908.8,4344) U2.14
  Top Layer w10: v2(3434,3784) 3438.79,3779.21 U5.45 3621.21,3779.21 v2(3622,3780) ; R1.2 3757.9,4320.44 C2.2 3728.44,4284 3825.76,4284 ; v2(3828,3714) 3828.79,3713.21 U5.63 ; U5.13 3828.79,4280.97 3825.76,4284 ; U5.9 3907.53,4284 ; 3907.53,4284.47 3907.53,4284 ; v2(4066,3760) 4065.52,3759.52 U5.80 ; v2(4094,3648) 4010,3732 4010,3750 4000,3760 v2(3973.39,3760) 3973.39,3809.71 3973.52,3809.83 3973.52,3835.52 4006,3868 4006,3956 4085.11,4035.11 U5.94 ; v2(4496,4316) 4465.2,4316 4416,4316 4308,4208 4252,4208 4242,4198 4150,4198 4064,4284 3907.53,4284 ; v2@4630,3644 4633.3,3640.7 4633.3,3615.2 U2.29@4633.3,3591.2 ; U2.43@4908.8,3599.2 4908.8,3563.2 v2(4920,3552) ; v2(5102,3552) 5105.7,3555.7 U2.53@5105.7,3599.2 ; 3825.76,4284 3907.53,4284
  Top Layer w18: v2(3658,4322) 3690.44,4322 C2.2
  Top Layer w24: 3246,3786 3248,3784
  Top Layer w40: 3246,3760 3246,3685.83 3287.33,3644.49 CART1.1 ; 3246,3764 3246,3786 v3(3246,3842)
  Bottom Layer w8: v2(3434,3784) 3450,3800 v2(3450,4054) ; v2(4496,4316) 4524,4344 v2(4908.8,4344)
  Bottom Layer w10: v2(3622,3780) 3690,3712 v2(3750,3712) 3826,3712 v2(3828,3714) 3927.39,3714 v2(3973.39,3760) v2(4066,3760) ; v2(4094,3648) 4096,3646 v2(4628,3646) 4896,3646 4920,3622 v2(4920,3552) v2(5102,3552)
  Bottom Layer w18: XP1.1 3214,4286 3308,4192 ; v3(3246,3842) 3246,4130 3308,4192 ; v2(3658,4322) 3572,4322 3442,4192 3308,4192
~CS2~: CART1.30 U4.30 U5.89 | length 1558.1
  Top Layer w6: U5.89 4165.31,3936.69 4184,3918 4184,3776 4236,3724 4306,3724 v1(4320,3710) ; v1(4616,3760) 4522.27,3666.27 U4.30 4522.27,3557.62 4545.41,3534.49 4855.51,3534.49 5009.95,3380.05 CART1.30
  Bottom Layer w6: v1(4320,3710) 4442,3710 4464,3732 4528,3732 4556,3760 v1(4616,3760)
~CS~: CART1.5 U2.32 U5.50 | length 1721.8
  Top Layer w6: U5.50 3591.22,3680.78 v1(3594,3678) ; U5.50@3529.17,3681.1 3481.1,3681.1 3462,3662 3462,3508 3533.57,3436.43 CART1.5 ; v1(4692,3556) 4692.3,3556.3 U2.32@4692.3,3599.2
  Bottom Layer w6: v1(3594,3678) 3692,3580 4558,3580 4582,3556 v1(4692,3556)
~RD~: CART1.4 U2.34 U4.32 U5.49 | length 1862.2
  Top Layer w6: CART1.4 3474,3306.78 3474,3435.43 3440.08,3469.35 3440.08,3674.08 3466,3700 v1(3610,3700) ; U4.32 4561.64,3590.36 4572,3580 v1(4598,3580) ; U2.34@4731.7,3599.2 4731.7,3556.3 v1(4732,3556)
  Bottom Layer w6: v1(3610,3700) 3716,3594 4584,3594 v1(4598,3580) 4708,3580 v1(4732,3556)
~WR~: CART1.3 U2.13 U4.5 U5.48 | length 2576.7
  Top Layer w6: CART1.3 3415.46,3683.46 3451.8,3719.8 3605.8,3719.8 3650,3764 3650,3934 3706,3990 v1(3906,3990) ; U4.5 4482.9,4027.1 v1(4488,4022) ; v1(4928,4084) 4928.5,4084.5 U2.13@4928.5,4378.8
  Bottom Layer w6: v1(3906,3990) 4009.29,3990 4029.29,3970 4248,3970 4256,3978 4444,3978 v1(4488,4022) 4504,4038 4820,4038 4866,4084 v1(4928,4084)
pads on no net: CART1.2 CART1.16 U2.16 U2.17 U2.27 U2.28 U2.30 U2.40 U2.55 U2.56 U4.9 U4.31 U5.12 U5.14 U5.27 U5.28 U5.29 U5.30 U5.33 U5.34 U5.37 U5.38 U5.39 U5.40 U5.41 U5.42 U5.43 U5.44 U5.62 U5.64 U5.67 U5.73 U5.74 U5.75 U5.76 U5.77 U5.78 U5.81 U5.82 U5.83 U5.84 U5.85 U5.86 U5.87 U5.88
copper on no net: | length 1466.9
  Top Layer w6: 3905.82,3595.01 3908,3592.83 3908,3536 3979.08,3464.92 4100.34,3464.92 v1(4104.88,3460.38) 4183.18,3382.09 4183.18,3306.26 ; 4541.95,3624.24 4541.95,3565.15 v1(4546,3561.1) ; 4542,3626.28 4542,3664 4564,3686 v1(4588,3686) ; 4849.8,3599.2 4849.8,3687.8 v1(4850,3688)
  Bottom Layer w6: v1(4104.88,3460.38) 4134.38,3460.38 4217.28,3543.28 4528.18,3543.28 v1(4546,3561.1) ; v1(4588,3686) 4848,3686 v1(4850,3688)

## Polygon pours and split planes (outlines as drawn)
GND on Bottom Layer (solid, remove dead copper, pour order 2): 3000,3010 5422,3010 5422,4546 3000,4546
GND on Top Layer (solid, remove dead copper): 3016,3000 5460,3000 5460,4530 3016,4530

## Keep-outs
Top Layer:
  region: 3069,3099.31 5334.2,3099.31 5334.2,3404 3069,3404
  region: 3664.11,4336 3920,4336 3920,4359.82 3664.11,4359.82
  region: 4162,3718 4192,3718 4192,3754.53 4162,3754.53
  region: 4993,3612 5063,3612 5063,3632 4993,3632
  region: 4399,4269.47 4399,4282.88 4317,4282.88 4317,4269.47
  region: 3742,3556 3882,3556 3882,3586 3742,3586
  region: 4332.89,3565 4472.89,3565 4472.89,3595 4332.89,3595
  region: 5111,3386 5111,3526 5081,3526 5081,3386
  region: 3160,4262.85 3577.08,4262.85 3577.08,4284 3160,4284
  region: 3406,4347.66 3440.19,4347.66 3440.19,4437 3406,4437
  region: 4617.66,4398 5180.4,4398 5180.4,4428 4617.66,4428
  region: 3861.63,4182.23 3893.58,4182.23 3893.58,4254.99 3861.63,4254.99
  region: 4493.16,4258.18 4479.74,4258.18 4479.74,4159.36 4493.16,4159.36
  region: 4626,3579.44 5180.41,3579.44 5180.41,3609.44 4626,3609.44
Bottom Layer:
  region: 3426,4367 3426,4437 3406,4437 3406,4367
  region: 3602.57,3533.36 3602.57,3661.36 3582.57,3661.36 3582.57,3533.36
  region: 5045,3448.54 5076.35,3448.54 5076.35,3559.45 5045,3559.45
  region: 3435,4284.5 3181,4284.5 3181,4264.5 3435,4264.5
  region: 5092.58,4175.12 5123.68,4171.21 5143.47,4328.65 5112.36,4332.56
Board Outline Layer:
  lines w10: 3175.9,3673.97 3208.3,3648.66 3208.3,3504 3244,3504 3244,3176.85 3251.83,3176.83 5183.13,3176.83 5183.13,3503.05 5218.83,3503.05 5218.83,3647.87 5249,3668.72 5249,4434 5245.31,4437.69 4343.61,4437.69 4343.61,4338.71 cw(c4210.93,4365.86) 4077.58,4342.2 4077.58,4437.69 3175.9,4437.69 3175.9,3673.97

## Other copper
Top Layer:
  drawing of 399 lines, arcs and shapes, not listed
Bottom Layer:
  drawing of 153 lines, arcs and shapes, not listed

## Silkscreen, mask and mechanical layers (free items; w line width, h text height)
Top Silkscreen Layer:
  lines w5.91: 3244,3499 5183.13,3499 5183.13,3504.07 3244,3504.07 3244,3499
  text "TDI" at 3329.57,4283.9 h35 r90
  text "TCK" at 3434.37,4269.8 h35 r90
  text "GND" at 3485.65,4269.8 h35 r90
  text "TDO" at 3282.1,4268.9 h35 r90
  text "TMS" at 3382.1,4268.9 h35 r90
  text "VCC" at 3231.1,4266.9 h35 r90
  text "Designed by Bread" at 4020.6,3456 h35
  text "Rev1.0" at 3800,3424 h35
  text "ChisFlash                F32S128V01" at 3439,3414 h78.74
  text "Layout by Mori" at 4020.6,3412.5 h35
